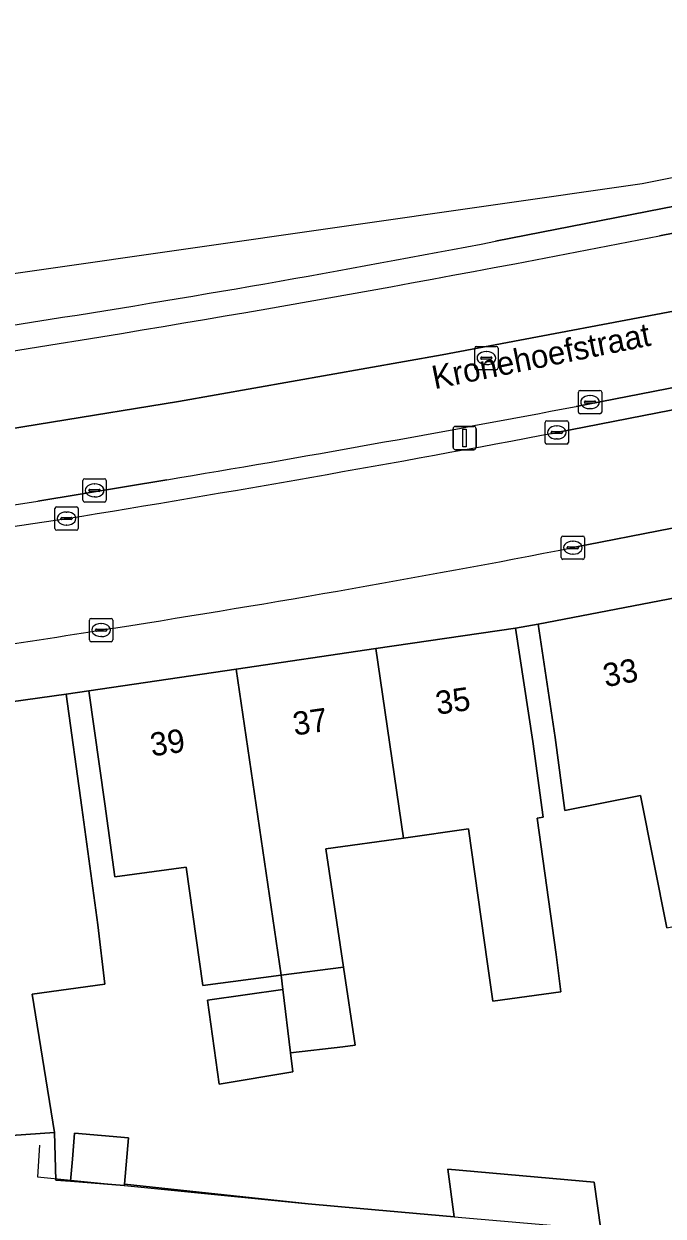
# Model space of a CAD drawing. Extents: x 160377 to 161131, y 383938 to 384853.
# Drawn here: x 160646 to 160673.4, y 384770.1 to 384821.3 of the extents above; entities that cross this region are included whole.
import ezdxf

# ---------------------------------------------------------------- set-up
doc = ezdxf.new("R2010")
doc.units = 0
for name, color, linetype in [('IMGEO_Berm_open', 7, 'Continuous'), ('IMGEO_Erf', 7, 'Continuous'), ('IMGEO_Hek', 7, 'Continuous'), ('IMGEO_Kolk', 7, 'Continuous'), ('IMGEO_Lichtmast', 7, 'Continuous'), ('IMGEO_Openbare_ruimte_label', 7, 'Continuous'), ('IMGEO_Pand', 7, 'Continuous'), ('IMGEO_Pand_nummerreeks', 7, 'Continuous'), ('IMGEO_Rijbaan_lokaal_open', 7, 'Continuous'), ('IMGEO_Rijbaan_regionaal_gesloten', 7, 'Continuous'), ('IMGEO_Rioolput', 7, 'Continuous'), ('IMGEO_Verkeerseiland_open', 7, 'Continuous'), ('IMGEO_Voetpad_open', 7, 'Continuous')]:
    doc.layers.add(name, color=color, linetype=linetype)

msp = doc.modelspace()

# ---------------------------------------------------------------- linework, layer by layer
at = {"layer": 'IMGEO_Berm_open'}
for points in [[(160753.962, 384821.317), (160669.687, 384804.898)], [(160668.863, 384803.782), (160690.315, 384807.978), (160710.765, 384811.973), (160731.557, 384816.055), (160751.991, 384820.036), (160754.132, 384820.304)], [(160652.133, 384801.749), (160646.598, 384800.833)]]:
    msp.add_lwpolyline(points, dxfattribs=at)
for centre, radius, start, end in [((160524.061, 385566.184), 775.089, 279.510897, 280.829259), ((160513.41, 385626.697), 837.469, 279.236446, 280.697447), ((160559.303, 385371.76), 577.562, 276.600495, 278.693253), ((160431.521, 386247.226), 1463.217, 277.890967, 278.501285)]:
    msp.add_arc(centre, radius, start, end, dxfattribs=at)
at = {"layer": 'IMGEO_Erf'}
msp.add_lwpolyline([(160673.583, 384782.519), (160672.449, 384788.196), (160669.214, 384787.549), (160668.794, 384790.685), (160668.056, 384795.549), (160667.094, 384795.385), (160667.829, 384790.524), (160668.283, 384787.267), (160668.014, 384787.231), (160668.831, 384781.382), (160669.036, 384779.774), (160666.121, 384779.379), (160665.889, 384780.971), (160665.079, 384786.764), (160662.291, 384786.374), (160658.952, 384785.908), (160659.714, 384780.836), (160660.218, 384777.481), (160659.677, 384777.417), (160657.434, 384777.15), (160657.531, 384776.334), (160654.374, 384775.815), (160653.875, 384779.41), (160657.112, 384779.872), (160657.031, 384780.488), (160653.671, 384780.052), (160652.962, 384785.131), (160649.902, 384784.703), (160649.465, 384787.841), (160648.788, 384792.69), (160647.807, 384792.552), (160648.48, 384787.689), (160649.177, 384782.645), (160649.466, 384780.104), (160646.349, 384779.673), (160647.308, 384773.741), (160647.375, 384771.691), (160648.003, 384771.651), (160648.082, 384772.588), (160648.176, 384773.704), (160650.481, 384773.509), (160650.313, 384771.513), (160658.202, 384770.669), (160660.432, 384770.475), (160664.465, 384770.123), (160664.192, 384772.157), (160670.466, 384771.611), (160670.75, 384769.575)], dxfattribs=at)
at = {"layer": 'IMGEO_Hek'}
msp.add_lwpolyline([(160646.672, 384773.187), (160646.579, 384771.827), (160658.202, 384770.669)], dxfattribs=at)
at = {"layer": 'IMGEO_Kolk'}
for p, q in [((160669.787, 384804.658), (160669.787, 384805.51)), ((160669.862, 384805.584), (160670.714, 384805.584)), ((160670.275, 384805.364), (160670.3, 384805.364)), ((160670.788, 384805.51), (160670.788, 384804.658)), ((160670.046, 384805.078), (160670.046, 384805.09)), ((160670.484, 384805.041), (160670.086, 384805.041)), ((160670.089, 384805.127), (160670.487, 384805.127)), ((160670.298, 384804.804), (160670.273, 384804.804)), ((160670.53, 384805.09), (160670.53, 384805.078)), ((160668.361, 384803.356), (160668.361, 384804.208)), ((160668.436, 384804.282), (160669.288, 384804.282)), ((160669.362, 384804.208), (160669.362, 384803.356)), ((160670.714, 384804.584), (160669.862, 384804.584)), ((160668.62, 384803.776), (160668.62, 384803.788)), ((160669.058, 384803.739), (160668.66, 384803.739)), ((160668.663, 384803.825), (160669.061, 384803.825)), ((160668.849, 384804.062), (160668.874, 384804.062)), ((160669.104, 384803.788), (160669.104, 384803.776)), ((160669.288, 384803.282), (160668.436, 384803.282)), ((160668.872, 384803.502), (160668.847, 384803.502)), ((160648.533, 384800.869), (160648.533, 384801.721)), ((160648.608, 384801.795), (160649.46, 384801.795)), ((160649.021, 384801.575), (160649.046, 384801.575)), ((160649.534, 384801.721), (160649.534, 384800.869)), ((160648.792, 384801.289), (160648.792, 384801.301)), ((160649.23, 384801.252), (160648.832, 384801.252)), ((160648.835, 384801.338), (160649.233, 384801.338)), ((160649.276, 384801.301), (160649.276, 384801.289)), ((160647.405, 384800.587), (160648.257, 384800.587)), ((160649.46, 384800.795), (160648.608, 384800.795)), ((160649.044, 384801.015), (160649.019, 384801.015)), ((160647.33, 384799.661), (160647.33, 384800.513)), ((160647.589, 384800.081), (160647.589, 384800.093)), ((160648.027, 384800.044), (160647.629, 384800.044)), ((160647.632, 384800.13), (160648.03, 384800.13)), ((160647.818, 384800.367), (160647.843, 384800.367)), ((160648.073, 384800.093), (160648.073, 384800.081)), ((160648.331, 384800.513), (160648.331, 384799.661)), ((160648.257, 384799.587), (160647.405, 384799.587)), ((160647.841, 384799.807), (160647.816, 384799.807)), ((160669.053, 384798.41), (160669.053, 384799.262)), ((160669.128, 384799.336), (160669.98, 384799.336)), ((160669.541, 384799.116), (160669.566, 384799.116)), ((160670.054, 384799.262), (160670.054, 384798.41)), ((160669.312, 384798.83), (160669.312, 384798.842)), ((160669.75, 384798.793), (160669.352, 384798.793)), ((160669.355, 384798.879), (160669.753, 384798.879)), ((160669.564, 384798.556), (160669.539, 384798.556)), ((160669.796, 384798.842), (160669.796, 384798.83)), ((160669.98, 384798.336), (160669.128, 384798.336)), ((160648.811, 384794.875), (160648.811, 384795.727)), ((160648.886, 384795.801), (160649.738, 384795.801)), ((160649.299, 384795.581), (160649.324, 384795.581)), ((160649.812, 384795.727), (160649.812, 384794.875)), ((160649.07, 384795.295), (160649.07, 384795.307)), ((160649.508, 384795.258), (160649.11, 384795.258)), ((160649.113, 384795.344), (160649.511, 384795.344)), ((160649.322, 384795.021), (160649.297, 384795.021)), ((160649.554, 384795.307), (160649.554, 384795.295)), ((160649.738, 384794.801), (160648.886, 384794.801))]:
    msp.add_line(p, q, dxfattribs=at)
for points in [[(160669.787, 384804.658), (160669.787, 384805.51)], [(160669.862, 384805.584), (160670.714, 384805.584)], [(160670.788, 384805.51), (160670.788, 384804.658)], [(160668.361, 384803.356), (160668.361, 384804.208)], [(160668.436, 384804.282), (160669.288, 384804.282)], [(160669.362, 384804.208), (160669.362, 384803.356)], [(160670.714, 384804.584), (160669.862, 384804.584)], [(160669.288, 384803.282), (160668.436, 384803.282)], [(160648.533, 384800.869), (160648.533, 384801.721)], [(160648.608, 384801.795), (160649.46, 384801.795)], [(160649.534, 384801.721), (160649.534, 384800.869)], [(160647.405, 384800.587), (160648.257, 384800.587)], [(160649.46, 384800.795), (160648.608, 384800.795)], [(160647.33, 384799.661), (160647.33, 384800.513)], [(160648.331, 384800.513), (160648.331, 384799.661)], [(160648.257, 384799.587), (160647.405, 384799.587)], [(160669.053, 384798.41), (160669.053, 384799.262)], [(160669.128, 384799.336), (160669.98, 384799.336)], [(160670.054, 384799.262), (160670.054, 384798.41)], [(160669.98, 384798.336), (160669.128, 384798.336)], [(160648.811, 384794.875), (160648.811, 384795.727)], [(160648.886, 384795.801), (160649.738, 384795.801)], [(160649.812, 384795.727), (160649.812, 384794.875)], [(160649.738, 384794.801), (160648.886, 384794.801)]]:
    msp.add_lwpolyline(points, dxfattribs=at)
for centre, radius, start, end in [((160669.864, 384805.508), 0.0765, 91.552, 178.448), ((160669.864, 384805.508), 0.0765, 91.552, 178.448), ((160670.712, 384805.508), 0.0765, 1.552, 88.448), ((160670.712, 384805.508), 0.0765, 1.552, 88.448), ((160669.864, 384804.66), 0.0765, 181.552, 268.448), ((160669.864, 384804.66), 0.0765, 181.552, 268.448), ((160670.086, 384805.087), 0.0403, 85.8775, 175.7526), ((160670.083, 384805.077), 0.0366, 178.938, 274.7102), ((160670.487, 384805.084), 0.043, 264.8664, 352.4533), ((160670.491, 384805.089), 0.0386, 1.7309, 96.639), ((160670.712, 384804.66), 0.0765, 271.552, 358.448), ((160670.712, 384804.66), 0.0765, 271.552, 358.448), ((160668.438, 384804.206), 0.0765, 91.552, 178.448), ((160668.438, 384804.206), 0.0765, 91.552, 178.448), ((160669.286, 384804.206), 0.0765, 1.552, 88.448), ((160669.286, 384804.206), 0.0765, 1.552, 88.448), ((160668.66, 384803.785), 0.0403, 85.8775, 175.7526), ((160668.657, 384803.775), 0.0366, 178.938, 274.7102), ((160669.061, 384803.782), 0.043, 264.8664, 352.4533), ((160669.065, 384803.787), 0.0386, 1.7309, 96.639), ((160668.438, 384803.358), 0.0765, 181.552, 268.448), ((160668.438, 384803.358), 0.0765, 181.552, 268.448), ((160669.286, 384803.358), 0.0765, 271.552, 358.448), ((160669.286, 384803.358), 0.0765, 271.552, 358.448), ((160648.61, 384801.719), 0.0765, 91.552, 178.448), ((160648.61, 384801.719), 0.0765, 91.552, 178.448), ((160649.458, 384801.719), 0.0765, 1.552, 88.448), ((160649.458, 384801.719), 0.0765, 1.552, 88.448), ((160648.832, 384801.298), 0.0403, 85.8775, 175.7526), ((160648.829, 384801.288), 0.0366, 178.938, 274.7102), ((160649.233, 384801.295), 0.043, 264.8664, 352.4533), ((160649.237, 384801.3), 0.0386, 1.7309, 96.639), ((160647.407, 384800.511), 0.0765, 91.552, 178.448), ((160647.407, 384800.511), 0.0765, 91.552, 178.448), ((160648.255, 384800.511), 0.0765, 1.552, 88.448), ((160648.255, 384800.511), 0.0765, 1.552, 88.448), ((160648.61, 384800.871), 0.0765, 181.552, 268.448), ((160648.61, 384800.871), 0.0765, 181.552, 268.448), ((160649.458, 384800.871), 0.0765, 271.552, 358.448), ((160649.458, 384800.871), 0.0765, 271.552, 358.448), ((160647.629, 384800.09), 0.0403, 85.8775, 175.7526), ((160647.626, 384800.08), 0.0366, 178.938, 274.7102), ((160648.03, 384800.087), 0.043, 264.8664, 352.4533), ((160648.034, 384800.092), 0.0386, 1.7309, 96.639), ((160647.407, 384799.663), 0.0765, 181.552, 268.448), ((160647.407, 384799.663), 0.0765, 181.552, 268.448), ((160648.255, 384799.663), 0.0765, 271.552, 358.448), ((160648.255, 384799.663), 0.0765, 271.552, 358.448), ((160669.13, 384799.26), 0.0765, 91.552, 178.448), ((160669.13, 384799.26), 0.0765, 91.552, 178.448), ((160669.978, 384799.26), 0.0765, 1.552, 88.448), ((160669.978, 384799.26), 0.0765, 1.552, 88.448), ((160669.352, 384798.839), 0.0403, 85.8775, 175.7526), ((160669.349, 384798.829), 0.0366, 178.938, 274.7102), ((160669.753, 384798.836), 0.043, 264.8664, 352.4533), ((160669.757, 384798.841), 0.0386, 1.7309, 96.639), ((160669.13, 384798.412), 0.0765, 181.552, 268.448), ((160669.13, 384798.412), 0.0765, 181.552, 268.448), ((160669.978, 384798.412), 0.0765, 271.552, 358.448), ((160669.978, 384798.412), 0.0765, 271.552, 358.448), ((160648.888, 384795.725), 0.0765, 91.552, 178.448), ((160648.888, 384795.725), 0.0765, 91.552, 178.448), ((160649.736, 384795.725), 0.0765, 1.552, 88.448), ((160649.736, 384795.725), 0.0765, 1.552, 88.448), ((160649.11, 384795.304), 0.0403, 85.8775, 175.7526), ((160649.107, 384795.294), 0.0366, 178.938, 274.7102), ((160649.511, 384795.301), 0.043, 264.8664, 352.4533), ((160649.515, 384795.306), 0.0386, 1.7309, 96.639), ((160648.888, 384794.877), 0.0765, 181.552, 268.448), ((160648.888, 384794.877), 0.0765, 181.552, 268.448), ((160649.736, 384794.877), 0.0765, 271.552, 358.448), ((160649.736, 384794.877), 0.0765, 271.552, 358.448)]:
    msp.add_arc(centre, radius, start, end, dxfattribs=at)
for centre, major_axis, ratio, start_param, end_param in [((160670.274, 384805.084), (-0.387, 0.002), 0.722429, 4.712389, 7.853982), ((160670.299, 384805.084), (-0.39, 0.002), 0.717154, 1.570796, 4.712389), ((160668.848, 384803.782), (-0.387, 0.002), 0.722429, 4.712389, 7.853982), ((160668.873, 384803.782), (-0.39, 0.002), 0.717154, 1.570796, 4.712389), ((160649.02, 384801.295), (-0.387, 0.002), 0.722429, 4.712389, 7.853982), ((160649.045, 384801.295), (-0.39, 0.002), 0.717154, 1.570796, 4.712389), ((160647.817, 384800.087), (-0.387, 0.002), 0.722429, 4.712389, 7.853982), ((160647.842, 384800.087), (-0.39, 0.002), 0.717154, 1.570796, 4.712389), ((160669.54, 384798.836), (-0.387, 0.002), 0.722429, 4.712389, 7.853982), ((160669.565, 384798.836), (-0.39, 0.002), 0.717154, 1.570796, 4.712389), ((160649.298, 384795.301), (-0.387, 0.002), 0.722429, 4.712389, 7.853982), ((160649.323, 384795.301), (-0.39, 0.002), 0.717154, 1.570796, 4.712389)]:
    msp.add_ellipse(centre, major_axis=major_axis, ratio=ratio, start_param=start_param, end_param=end_param, dxfattribs=at)
at = {"layer": 'IMGEO_Lichtmast'}
for p, q in [((160664.41, 384803.142), (160664.41, 384803.942)), ((160664.41, 384803.942), (160664.41, 384803.142)), ((160664.51, 384804.042), (160665.3, 384804.042)), ((160665.3, 384804.042), (160664.51, 384804.042)), ((160665.4, 384803.942), (160665.4, 384803.142)), ((160665.4, 384803.142), (160665.4, 384803.942)), ((160665.3, 384803.042), (160664.51, 384803.042)), ((160664.51, 384803.042), (160665.3, 384803.042))]:
    msp.add_line(p, q, dxfattribs=at)
msp.add_lwpolyline([(160664.83, 384803.917), (160664.98, 384803.917), (160664.98, 384803.167), (160664.83, 384803.167), (160664.83, 384803.917)], dxfattribs=at)
for centre, start, end in [((160664.51, 384803.942), 90, 180), ((160664.51, 384803.942), 90, 180), ((160665.3, 384803.942), 0, 90), ((160665.3, 384803.942), 360, 90), ((160664.51, 384803.142), 180, 270), ((160664.51, 384803.142), 180, 270), ((160665.3, 384803.142), 270, 0), ((160665.3, 384803.142), 270, 0)]:
    msp.add_arc(centre, 0.1, start, end, dxfattribs=at)
at = {"layer": 'IMGEO_Pand'}
for points in [[(160674.38, 384796.767), (160668.056, 384795.549), (160668.794, 384790.685), (160669.214, 384787.549), (160672.449, 384788.196), (160673.583, 384782.519), (160674.969, 384782.796), (160676.988, 384783.2)], [(160667.829, 384790.524), (160667.094, 384795.385), (160661.103, 384794.503), (160662.291, 384786.374), (160665.079, 384786.764), (160665.889, 384780.971), (160666.121, 384779.379), (160669.036, 384779.774), (160668.831, 384781.382), (160668.014, 384787.231), (160668.283, 384787.267)], [(160662.291, 384786.374), (160661.103, 384794.503), (160655.111, 384793.621), (160657.031, 384780.488), (160659.714, 384780.836), (160658.952, 384785.908)], [(160655.111, 384793.621), (160648.788, 384792.69), (160649.465, 384787.841), (160649.902, 384784.703), (160652.962, 384785.131), (160653.671, 384780.052), (160657.031, 384780.488)], [(160648.48, 384787.689), (160647.807, 384792.552), (160641.141, 384791.616), (160643.812, 384773.488), (160647.308, 384773.741), (160646.349, 384779.673), (160649.466, 384780.104), (160649.177, 384782.645)], [(160659.714, 384780.836), (160657.031, 384780.488), (160657.112, 384779.872), (160657.434, 384777.15), (160659.677, 384777.417), (160660.218, 384777.481)], [(160657.112, 384779.872), (160653.875, 384779.41), (160654.374, 384775.815), (160657.531, 384776.334), (160657.434, 384777.15)], [(160648.082, 384772.588), (160648.003, 384771.651), (160650.308, 384771.457), (160650.313, 384771.513), (160650.481, 384773.509), (160648.176, 384773.704)], [(160664.192, 384772.157), (160664.465, 384770.123), (160670.75, 384769.575), (160670.466, 384771.611)]]:
    msp.add_lwpolyline(points, close=True, dxfattribs=at)
at = {"layer": 'IMGEO_Rijbaan_lokaal_open'}
for points in [[(160745.246, 384813.658), (160756.944, 384815.951), (160756.782, 384816.801), (160754.132, 384820.304), (160751.991, 384820.036), (160731.557, 384816.055), (160710.765, 384811.973), (160690.315, 384807.978), (160668.863, 384803.782)], [(160669.558, 384798.838), (160712.036, 384807.136)]]:
    msp.add_lwpolyline(points, dxfattribs=at)
for centre, radius, start, end in [((160513.41, 385626.697), 837.469, 279.236446, 280.697447), ((160431.521, 386247.226), 1463.217, 277.890967, 278.501285), ((160566.781, 385327.634), 538.691, 278.81322, 280.9989), ((160553.042, 385393.579), 605.972, 277.975051, 279.141593)]:
    msp.add_arc(centre, radius, start, end, dxfattribs=at)
at = {"layer": 'IMGEO_Rijbaan_regionaal_gesloten'}
for points in [[(160821.599, 384844.146), (160829.468, 384845.895), (160829.618, 384845.927), (160829.254, 384846.905), (160806.499, 384841.714), (160790.719, 384838.114), (160734.589, 384826.879), (160672.527, 384814.457), (160614.171, 384806.098), (160545.148, 384802.929), (160536.931, 384801.145)], [(160620.019, 384800.647), (160623.941, 384800.965), (160636.271, 384802.448), (160652.633, 384805.11), (160663.941, 384807.107), (160687.886, 384811.633), (160723.538, 384818.688), (160757.394, 384825.337), (160773.567, 384827.732), (160796.581, 384831.06), (160808.154, 384832.524), (160820.659, 384834.653), (160832.812, 384837.187), (160831.861, 384840.102), (160818.009, 384837.306), (160805.372, 384835.31), (160791.27, 384833.313), (160761.012, 384829.451), (160759.855, 384829.172), (160673.267, 384812.223)], [(160666.233, 384811.987), (160791.269, 384836.471), (160798.406, 384838.282)], [(160833.826, 384834.082), (160832.812, 384837.187), (160820.659, 384834.653), (160808.154, 384832.524), (160796.581, 384831.06), (160773.567, 384827.732), (160757.394, 384825.337), (160723.538, 384818.688), (160687.886, 384811.633), (160663.941, 384807.107), (160652.633, 384805.11), (160636.271, 384802.448), (160623.941, 384800.965), (160620.019, 384800.647)], [(160669.687, 384804.898), (160753.962, 384821.317)], [(160646.598, 384800.833), (160652.133, 384801.749)]]:
    msp.add_lwpolyline(points, dxfattribs=at)
for centre, radius, start, end in [((160562.133, 385349.737), 547.733, 276.74718, 280.95609), ((160527.046, 385551.759), 753.853, 278.990121, 281.184276), ((160524.061, 385566.184), 775.089, 279.510897, 280.829259), ((160559.303, 385371.76), 577.562, 276.600495, 278.693253)]:
    msp.add_arc(centre, radius, start, end, dxfattribs=at)
at = {"layer": 'IMGEO_Rioolput'}
for p, q in [((160665.339, 384806.549), (160665.339, 384807.401)), ((160665.414, 384807.475), (160666.266, 384807.475)), ((160665.827, 384807.255), (160665.852, 384807.255)), ((160666.34, 384807.401), (160666.34, 384806.549)), ((160665.598, 384806.969), (160665.598, 384806.981)), ((160666.036, 384806.932), (160665.638, 384806.932)), ((160665.641, 384807.018), (160666.039, 384807.018)), ((160665.85, 384806.695), (160665.825, 384806.695)), ((160666.082, 384806.981), (160666.082, 384806.969)), ((160666.266, 384806.475), (160665.414, 384806.475))]:
    msp.add_line(p, q, dxfattribs=at)
for points in [[(160665.339, 384806.549), (160665.339, 384807.401)], [(160665.414, 384807.475), (160666.266, 384807.475)], [(160666.34, 384807.401), (160666.34, 384806.549)], [(160666.266, 384806.475), (160665.414, 384806.475)]]:
    msp.add_lwpolyline(points, dxfattribs=at)
for centre, radius, start, end in [((160665.416, 384807.399), 0.0765, 91.552, 178.448), ((160665.416, 384807.399), 0.0765, 91.552, 178.448), ((160666.264, 384807.399), 0.0765, 1.552, 88.448), ((160666.264, 384807.399), 0.0765, 1.552, 88.448), ((160665.638, 384806.978), 0.0403, 85.8775, 175.7526), ((160665.635, 384806.968), 0.0366, 178.938, 274.7102), ((160666.039, 384806.975), 0.043, 264.8664, 352.4533), ((160666.043, 384806.98), 0.0386, 1.7309, 96.639), ((160665.416, 384806.551), 0.0765, 181.552, 268.448), ((160665.416, 384806.551), 0.0765, 181.552, 268.448), ((160666.264, 384806.551), 0.0765, 271.552, 358.448), ((160666.264, 384806.551), 0.0765, 271.552, 358.448)]:
    msp.add_arc(centre, radius, start, end, dxfattribs=at)
for centre, major_axis, ratio, start_param, end_param in [((160665.826, 384806.975), (-0.387, 0.002), 0.722429, 4.712389, 7.853982), ((160665.851, 384806.975), (-0.39, 0.002), 0.717154, 1.570796, 4.712389)]:
    msp.add_ellipse(centre, major_axis=major_axis, ratio=ratio, start_param=start_param, end_param=end_param, dxfattribs=at)
at = {"layer": 'IMGEO_Verkeerseiland_open'}
msp.add_lwpolyline([(160673.267, 384812.223), (160759.855, 384829.172), (160761.012, 384829.451), (160791.519, 384835.419), (160791.269, 384836.471), (160666.233, 384811.987)], dxfattribs=at)
for centre, radius, start, end in [((160562.133, 385349.737), 547.733, 276.74718, 280.95609), ((160527.046, 385551.759), 753.853, 278.990121, 281.184276)]:
    msp.add_arc(centre, radius, start, end, dxfattribs=at)
at = {"layer": 'IMGEO_Voetpad_open'}
for points in [[(160732.219, 384810.957), (160731.148, 384810.84), (160712.036, 384807.136), (160669.558, 384798.838)], [(160622.22, 384787.392), (160625.386, 384788.399), (160626.181, 384789.448), (160634.124, 384790.626), (160634.642, 384790.703), (160641.141, 384791.616), (160647.807, 384792.552), (160648.788, 384792.69), (160655.111, 384793.621), (160661.103, 384794.503), (160667.094, 384795.385), (160668.056, 384795.549), (160674.38, 384796.767), (160680.098, 384797.869), (160680.864, 384796.949), (160702.668, 384801.211)], [(160664.465, 384770.123), (160660.432, 384770.475), (160658.202, 384770.669), (160650.313, 384771.513), (160650.308, 384771.457), (160648.003, 384771.651), (160647.375, 384771.691), (160647.308, 384773.741), (160643.812, 384773.488), (160639.925, 384772.701), (160635.254, 384772.107), (160633.903, 384771.935), (160633.528, 384774.911), (160632.132, 384774.718), (160627.458, 384774.072), (160628.436, 384764.964)]]:
    msp.add_lwpolyline(points, dxfattribs=at)
for centre, radius, start, end in [((160566.781, 385327.634), 538.691, 278.81322, 280.9989), ((160553.042, 385393.579), 605.972, 277.975051, 279.141593)]:
    msp.add_arc(centre, radius, start, end, dxfattribs=at)

# ---------------------------------------------------------------- texts
at = {"layer": 'IMGEO_Openbare_ruimte_label'}
msp.add_text('Kronehoefstraat', height=1, rotation=11.4223, dxfattribs=at).set_placement((160663.617, 384805.635))
at = {"layer": 'IMGEO_Pand_nummerreeks'}
for s, rotation, p in [('33', 10.8968, (160670.951, 384792.842)), ('35', 8.3136, (160663.734, 384791.663)), ('37', 8.3122, (160657.612, 384790.768)), ('39', 8.3122, (160651.491, 384789.874))]:
    msp.add_text(s, height=1, rotation=rotation, dxfattribs=at).set_placement(p)

doc.saveas('drawing.dxf')
